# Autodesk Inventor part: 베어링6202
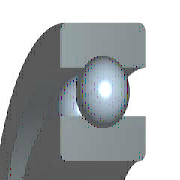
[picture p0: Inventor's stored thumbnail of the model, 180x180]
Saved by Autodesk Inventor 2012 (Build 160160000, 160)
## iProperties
IsCustomPart: 0
Company: 한국ATC센터
Created: 2014-12
Part Number: 베어링6202
Material: 강, 연강
Description: 깊은 그루브 볼 베어링
Document SubType Name: Modeling
Standard: KS B 2023
Designer: KYOUNG IL JANG
Standards Organization: KS
Language: ko-KR
Size Designation: 6202 - 15 x 35 x 11
Categories: <MemberInstance><Categories><Category DisplayName="샤프트 부품" InternalName="7f7aeb1f-a693-4053-b835-cee3144e0d98" Mnemonic="SHFT"><Category DisplayName="베어링" Inter
Density: 7.86 g/cm^3
Mass: 45.8725 g
Surface Area: 51.5584 cm^2
Volume: 5.83619 cm^3
Author: KYOUNG IL JANG
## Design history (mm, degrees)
revolve "본체" stored, may be unused: angle "d6" = 90 deg
revolve "볼" stored, may be unused: angle "d7" = 90 deg
pattern_circular "IDS_ARRAYBALL[SIMPL:T]" dims angle "d3" = 360 deg
body "Solid1"
sketch "스케치" dims "d0" = 5.2 (= -0.26 x WD + 0.26 x BD)
  geometry: L1 (2.9, 12.5)-(8.1, 12.5); L2 (5.5, 12.5)-(5.5, 9.9); L3 (5.5, 12.5)-(5.5, 15.1); L4 (3.568, 10.76)-(0, 10.76); L5 (0, 7.5)-(11, 7.5); L6 (3.568, 14.24)-(0, 14.24); L7 (0, 17.5)-(11, 17.5); L8 (11, 7.5)-(11, 10.76); L9 (7.432, 10.76)-(11, 10.76); L10 (7.432, 14.24)-(11, 14.24); L11 (11, 17.5)-(11, 14.24); L12 (-1.4, 0)-(8.4, 0) reference; L13 (0, -0.3)-(0, 5.3) reference
  constraints: 22 end point, 4 point on line, 2 collinear, 2 perpendicular, 2 symmetric about line, 1 midpoint, 1 parallel, 14 other
  dimensions: "d9" = 15 diameter of L5 L12 (= WD); "d11" = 35 diameter of L7 L12 (= BD); "d12" = 11 distance between parallel lines of L8 L13 (= KB); "d13" = 21.52 diameter of L9 L12 (= 0.326 x BD + 0.674 x WD)
fillet "모깎기1" dims "d1" = 0.6 (= KRS)
other parameters: "WD" = 15 [user parameter; used in 5 equation terms], "BD" = 35 [user parameter; used in 5 equation terms], "KB" = 11 [user parameter; used in 1 equation term], "KRS" = 0.6 [user parameter; used in 1 equation term], "d4" = 0, "d5" = 0, "d8" = 0, "d14" = 0, "d15" = 0, "BBA" = 0 [user parameter], "BC0" = 3750000 [user parameter], "BC" = 7800000 [user parameter], "BR" = 17.5 (= 0.5 x BD) [user parameter], "WR" = 7.5 (= 0.5 x WD) [user parameter]
